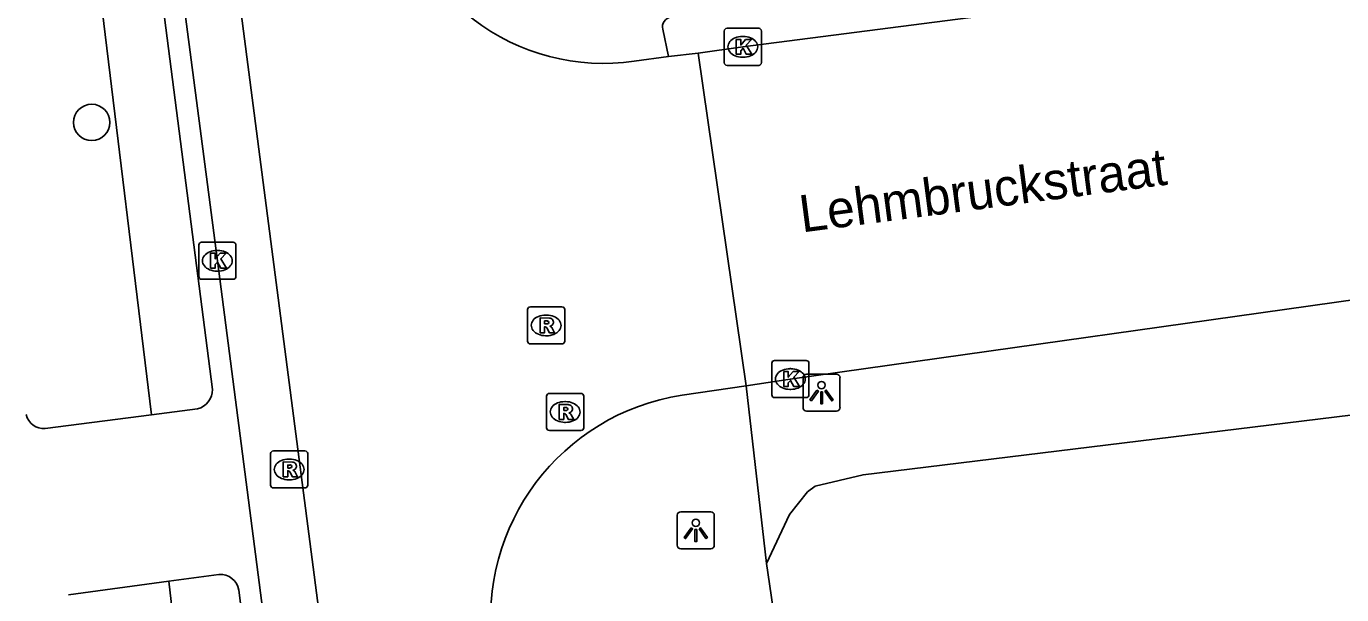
# Model space of a CAD drawing. Extents: x 160557 to 161245, y 385330 to 386505.
# Drawn here: x 161105.66 to 161141.1, y 385716.99 to 385732.31 of the extents above; entities that cross this region are included whole.
import ezdxf

# ---------------------------------------------------------------- set-up
doc = ezdxf.new("R2010")
doc.units = 0
for name, color, linetype in [('IMGEO_Boom', 7, 'Continuous'), ('IMGEO_Fietspad_gesloten', 7, 'Continuous'), ('IMGEO_Groenvoorziening', 7, 'Continuous'), ('IMGEO_Kolk', 7, 'Continuous'), ('IMGEO_Lichtpunt', 7, 'Continuous'), ('IMGEO_Openbare_ruimte_label', 7, 'Continuous'), ('IMGEO_Rijbaan_lokaal_gesloten', 7, 'Continuous'), ('IMGEO_Rijbaan_lokaal_open', 7, 'Continuous'), ('IMGEO_Rioolput', 7, 'Continuous'), ('IMGEO_Voetpad_open', 7, 'Continuous')]:
    doc.layers.add(name, color=color, linetype=linetype)

msp = doc.modelspace()

# ---------------------------------------------------------------- linework, layer by layer
at = {"layer": 'IMGEO_Boom'}
msp.add_circle((161107.423, 385729.722), 0.489, dxfattribs=at)
at = {"layer": 'IMGEO_Fietspad_gesloten'}
msp.add_lwpolyline([(161122.962, 385731.503), (161122.809, 385732.234)], dxfattribs=at)
msp.add_arc((161123.066, 385732.296), 0.265, 96.3414, 193.5563, dxfattribs=at)
at = {"layer": 'IMGEO_Groenvoorziening'}
for points in [[(161107.656, 385733.133), (161109.037, 385721.838)], [(161109.498, 385717.352), (161110.302, 385710.38)]]:
    msp.add_lwpolyline(points, dxfattribs=at)
at = {"layer": 'IMGEO_Kolk'}
for p, q in [((161124.466, 385731.334), (161124.466, 385732.186)), ((161124.541, 385732.26), (161125.393, 385732.26)), ((161124.954, 385732.04), (161124.979, 385732.04)), ((161125.467, 385732.186), (161125.467, 385731.334)), ((161124.977, 385731.48), (161124.952, 385731.48)), ((161125.393, 385731.26), (161124.541, 385731.26)), ((161110.307, 385725.566), (161110.307, 385726.418)), ((161110.382, 385726.492), (161111.234, 385726.492)), ((161111.308, 385726.418), (161111.308, 385725.566)), ((161110.795, 385726.272), (161110.82, 385726.272)), ((161110.818, 385725.712), (161110.793, 385725.712)), ((161111.234, 385725.492), (161110.382, 385725.492)), ((161125.747, 385722.376), (161125.747, 385723.228)), ((161125.822, 385723.302), (161126.674, 385723.302)), ((161126.748, 385723.228), (161126.748, 385722.376)), ((161126.235, 385723.082), (161126.26, 385723.082)), ((161126.258, 385722.522), (161126.233, 385722.522)), ((161126.674, 385722.302), (161125.822, 385722.302))]:
    msp.add_line(p, q, dxfattribs=at)
for points in [[(161124.466, 385731.334), (161124.466, 385732.186)], [(161124.541, 385732.26), (161125.393, 385732.26)], [(161125.467, 385732.186), (161125.467, 385731.334)], [(161124.787, 385731.96), (161124.91, 385731.96), (161124.91, 385731.809), (161125.04, 385731.96), (161125.204, 385731.96), (161125.058, 385731.809), (161125.211, 385731.56), (161125.059, 385731.56), (161124.974, 385731.724), (161124.91, 385731.657), (161124.91, 385731.56), (161124.787, 385731.56), (161124.787, 385731.96)], [(161125.393, 385731.26), (161124.541, 385731.26)], [(161110.307, 385725.566), (161110.307, 385726.418)], [(161110.382, 385726.492), (161111.234, 385726.492)], [(161111.308, 385726.418), (161111.308, 385725.566)], [(161110.628, 385726.192), (161110.751, 385726.192), (161110.751, 385726.041), (161110.881, 385726.192), (161111.045, 385726.192), (161110.899, 385726.041), (161111.052, 385725.792), (161110.9, 385725.792), (161110.815, 385725.956), (161110.751, 385725.889), (161110.751, 385725.792), (161110.628, 385725.792), (161110.628, 385726.192)], [(161111.234, 385725.492), (161110.382, 385725.492)], [(161125.747, 385722.376), (161125.747, 385723.228)], [(161125.822, 385723.302), (161126.674, 385723.302)], [(161126.748, 385723.228), (161126.748, 385722.376)], [(161126.068, 385723.002), (161126.191, 385723.002), (161126.191, 385722.851), (161126.321, 385723.002), (161126.485, 385723.002), (161126.339, 385722.851), (161126.492, 385722.602), (161126.34, 385722.602), (161126.255, 385722.766), (161126.191, 385722.699), (161126.191, 385722.602), (161126.068, 385722.602), (161126.068, 385723.002)], [(161126.674, 385722.302), (161125.822, 385722.302)]]:
    msp.add_lwpolyline(points, dxfattribs=at)
for centre, start, end in [((161124.543, 385732.184), 91.552, 178.448), ((161124.543, 385732.184), 91.552, 178.448), ((161125.391, 385732.184), 1.552, 88.448), ((161125.391, 385732.184), 1.552, 88.448), ((161124.543, 385731.336), 181.552, 268.448), ((161124.543, 385731.336), 181.552, 268.448), ((161125.391, 385731.336), 271.552, 358.448), ((161125.391, 385731.336), 271.552, 358.448), ((161110.384, 385726.416), 91.552, 178.448), ((161110.384, 385726.416), 91.552, 178.448), ((161111.232, 385726.416), 1.552, 88.448), ((161111.232, 385726.416), 1.552, 88.448), ((161110.384, 385725.568), 181.552, 268.448), ((161110.384, 385725.568), 181.552, 268.448), ((161111.232, 385725.568), 271.552, 358.448), ((161111.232, 385725.568), 271.552, 358.448), ((161125.824, 385723.226), 91.552, 178.448), ((161125.824, 385723.226), 91.552, 178.448), ((161126.672, 385723.226), 1.552, 88.448), ((161126.672, 385723.226), 1.552, 88.448), ((161125.824, 385722.378), 181.552, 268.448), ((161125.824, 385722.378), 181.552, 268.448), ((161126.672, 385722.378), 271.552, 358.448), ((161126.672, 385722.378), 271.552, 358.448)]:
    msp.add_arc(centre, 0.0765, start, end, dxfattribs=at)
for centre, major_axis, ratio, start_param, end_param in [((161124.953, 385731.76), (-0.387, 0.002), 0.722429, 4.712389, 7.853982), ((161124.978, 385731.76), (-0.39, 0.002), 0.717154, 1.570796, 4.712389), ((161110.794, 385725.992), (-0.387, 0.002), 0.722429, 4.712389, 7.853982), ((161110.819, 385725.992), (-0.39, 0.002), 0.717154, 1.570796, 4.712389), ((161126.234, 385722.802), (-0.387, 0.002), 0.722429, 4.712389, 7.853982), ((161126.259, 385722.802), (-0.39, 0.002), 0.717154, 1.570796, 4.712389)]:
    msp.add_ellipse(centre, major_axis=major_axis, ratio=ratio, start_param=start_param, end_param=end_param, dxfattribs=at)
at = {"layer": 'IMGEO_Lichtpunt'}
for p, q in [((161126.588, 385722.841), (161126.588, 385722.034)), ((161126.588, 385722.841), (161126.588, 385722.034)), ((161127.49, 385722.936), (161126.682, 385722.936)), ((161127.49, 385722.936), (161126.682, 385722.936)), ((161127.584, 385722.034), (161127.584, 385722.841)), ((161127.584, 385722.034), (161127.584, 385722.841)), ((161126.682, 385721.94), (161127.49, 385721.94)), ((161126.682, 385721.94), (161127.49, 385721.94)), ((161124.103, 385719.222), (161123.295, 385719.222)), ((161124.103, 385719.222), (161123.295, 385719.222)), ((161123.201, 385719.127), (161123.201, 385718.32)), ((161123.201, 385719.127), (161123.201, 385718.32)), ((161124.197, 385718.32), (161124.197, 385719.127)), ((161124.197, 385718.32), (161124.197, 385719.127)), ((161123.295, 385718.226), (161124.103, 385718.226)), ((161123.295, 385718.226), (161124.103, 385718.226))]:
    msp.add_line(p, q, dxfattribs=at)
for points in [[(161126.962, 385722.505), (161127.001, 385722.477), (161126.813, 385722.215), (161126.775, 385722.242), (161126.962, 385722.505)], [(161127.064, 385722.457), (161127.111, 385722.457), (161127.111, 385722.135), (161127.064, 385722.135), (161127.064, 385722.457)], [(161127.174, 385722.477), (161127.212, 385722.504), (161127.399, 385722.242), (161127.36, 385722.214), (161127.174, 385722.477)], [(161123.575, 385718.791), (161123.614, 385718.763), (161123.426, 385718.501), (161123.388, 385718.528), (161123.575, 385718.791)], [(161123.677, 385718.743), (161123.724, 385718.743), (161123.724, 385718.421), (161123.677, 385718.421), (161123.677, 385718.743)], [(161123.787, 385718.763), (161123.825, 385718.79), (161124.012, 385718.528), (161123.973, 385718.5), (161123.787, 385718.763)]]:
    msp.add_lwpolyline(points, dxfattribs=at)
for centre in [(161127.087, 385722.639), (161123.7, 385718.925)]:
    msp.add_circle(centre, 0.0994, dxfattribs=at)
for centre, start, end in [((161126.682, 385722.841), 90, 180), ((161126.682, 385722.841), 90, 180), ((161127.49, 385722.841), 0, 90), ((161127.49, 385722.841), 0, 90), ((161126.682, 385722.034), 180, 270), ((161126.682, 385722.034), 180, 270), ((161127.49, 385722.034), 270, 0), ((161127.49, 385722.034), 270, 360), ((161123.295, 385719.127), 90, 180), ((161123.295, 385719.127), 90, 180), ((161124.103, 385719.127), 0, 90), ((161124.103, 385719.127), 0, 90), ((161123.295, 385718.32), 180, 270), ((161123.295, 385718.32), 180, 270), ((161124.103, 385718.32), 270, 0), ((161124.103, 385718.32), 270, 360)]:
    msp.add_arc(centre, 0.0946, start, end, dxfattribs=at)
at = {"layer": 'IMGEO_Rijbaan_lokaal_gesloten'}
for points in [[(161156.186, 385735.803), (161142.998, 385734.087), (161140.183, 385733.73), (161124.967, 385731.76), (161123.761, 385731.592)], [(161112.32, 385714.335), (161110.808, 385725.992), (161109.906, 385732.917), (161109.885, 385733.092)], [(161148.145, 385725.902), (161142.936, 385725.157), (161126.238, 385722.801), (161125.06, 385722.618)]]:
    msp.add_lwpolyline(points, dxfattribs=at)
at = {"layer": 'IMGEO_Rijbaan_lokaal_open'}
for points in [[(161109.114, 385739.295), (161110.567, 385739.457), (161113.803, 385714.55), (161112.32, 385714.335)], [(161122.962, 385731.503), (161122.041, 385731.376)], [(161123.761, 385731.592), (161122.962, 385731.503)], [(161125.06, 385722.618), (161123.761, 385731.592)], [(161123.329, 385722.367), (161125.06, 385722.618)]]:
    msp.add_lwpolyline(points, dxfattribs=at)
for centre, radius, start, end in [((161121.199, 385737.038), 5.725, 186.1502, 278.4614), ((161124.257, 385716.353), 6.085, 98.7712, 187.3487)]:
    msp.add_arc(centre, radius, start, end, dxfattribs=at)
at = {"layer": 'IMGEO_Rioolput'}
for p, q in [((161119.166, 385723.823), (161119.166, 385724.675)), ((161119.241, 385724.749), (161120.093, 385724.749)), ((161120.167, 385724.675), (161120.167, 385723.823)), ((161119.654, 385724.529), (161119.679, 385724.529)), ((161119.677, 385723.969), (161119.652, 385723.969)), ((161120.093, 385723.749), (161119.241, 385723.749)), ((161119.754, 385722.414), (161120.606, 385722.414)), ((161119.679, 385721.488), (161119.679, 385722.34)), ((161120.167, 385722.194), (161120.192, 385722.194)), ((161120.68, 385722.34), (161120.68, 385721.488)), ((161120.606, 385721.414), (161119.754, 385721.414)), ((161120.19, 385721.634), (161120.165, 385721.634)), ((161112.242, 385719.939), (161112.242, 385720.791)), ((161112.317, 385720.865), (161113.169, 385720.865)), ((161112.73, 385720.645), (161112.755, 385720.645)), ((161113.243, 385720.791), (161113.243, 385719.939)), ((161112.753, 385720.085), (161112.728, 385720.085)), ((161113.169, 385719.865), (161112.317, 385719.865))]:
    msp.add_line(p, q, dxfattribs=at)
for points in [[(161119.166, 385723.823), (161119.166, 385724.675)], [(161119.241, 385724.749), (161120.093, 385724.749)], [(161120.167, 385724.675), (161120.167, 385723.823)], [(161119.755, 385724.447), (161119.503, 385724.449), (161119.503, 385724.049)], [(161119.503, 385724.049), (161119.627, 385724.049), (161119.627, 385724.211), (161119.638, 385724.211)], [(161119.681, 385724.368), (161119.627, 385724.368), (161119.627, 385724.287)], [(161119.627, 385724.287), (161119.679, 385724.287)], [(161119.685, 385724.182), (161119.756, 385724.049), (161119.896, 385724.049), (161119.831, 385724.175)], [(161120.093, 385723.749), (161119.241, 385723.749)], [(161119.754, 385722.414), (161120.606, 385722.414)], [(161119.679, 385721.488), (161119.679, 385722.34)], [(161120.268, 385722.112), (161120.016, 385722.114), (161120.016, 385721.714)], [(161120.68, 385722.34), (161120.68, 385721.488)], [(161120.016, 385721.714), (161120.14, 385721.714), (161120.14, 385721.876), (161120.151, 385721.876)], [(161120.194, 385722.033), (161120.14, 385722.033), (161120.14, 385721.952)], [(161120.14, 385721.952), (161120.192, 385721.952)], [(161120.198, 385721.847), (161120.269, 385721.714), (161120.409, 385721.714), (161120.344, 385721.84)], [(161120.606, 385721.414), (161119.754, 385721.414)], [(161112.242, 385719.939), (161112.242, 385720.791)], [(161112.317, 385720.865), (161113.169, 385720.865)], [(161113.243, 385720.791), (161113.243, 385719.939)], [(161112.831, 385720.563), (161112.579, 385720.565), (161112.579, 385720.165)], [(161112.579, 385720.165), (161112.703, 385720.165), (161112.703, 385720.327), (161112.714, 385720.327)], [(161112.757, 385720.484), (161112.703, 385720.484), (161112.703, 385720.403)], [(161112.703, 385720.403), (161112.755, 385720.403)], [(161112.761, 385720.298), (161112.832, 385720.165), (161112.972, 385720.165), (161112.907, 385720.291)], [(161113.169, 385719.865), (161112.317, 385719.865)]]:
    msp.add_lwpolyline(points, dxfattribs=at)
for centre, radius, start, end in [((161119.243, 385724.673), 0.0765, 91.552, 178.448), ((161119.243, 385724.673), 0.0765, 91.552, 178.448), ((161120.091, 385724.673), 0.0765, 1.552, 88.448), ((161120.091, 385724.673), 0.0765, 1.552, 88.448), ((161119.637, 385724.158), 0.0533, 26.0293, 88.6989), ((161119.663, 385724.476), 0.19, 274.7715, 282.9687), ((161119.687, 385724.272), 0.0964, 77.0061, 93.1865), ((161119.701, 385724.329), 0.0378, 276.6634, 79.6772), ((161119.754, 385724.337), 0.109, 350.3612, 89.416), ((161119.752, 385724.337), 0.112, 277.5842, 350.9817), ((161119.736, 385724.122), 0.108, 29.5134, 73.7905), ((161119.243, 385723.825), 0.0765, 181.552, 268.448), ((161119.243, 385723.825), 0.0765, 181.552, 268.448), ((161120.091, 385723.825), 0.0765, 271.552, 358.448), ((161120.091, 385723.825), 0.0765, 271.552, 358.448), ((161119.756, 385722.338), 0.0765, 91.552, 178.448), ((161119.756, 385722.338), 0.0765, 91.552, 178.448), ((161120.604, 385722.338), 0.0765, 1.552, 88.448), ((161120.604, 385722.338), 0.0765, 1.552, 88.448), ((161120.267, 385722.002), 0.109, 350.3612, 89.416), ((161120.15, 385721.823), 0.0533, 26.0293, 88.6989), ((161120.176, 385722.141), 0.19, 274.7715, 282.9687), ((161120.2, 385721.937), 0.0964, 77.0061, 93.1865), ((161120.214, 385721.994), 0.0378, 276.6634, 79.6772), ((161120.265, 385722.002), 0.112, 277.5842, 350.9817), ((161120.249, 385721.787), 0.108, 29.5134, 73.7905), ((161119.756, 385721.49), 0.0765, 181.552, 268.448), ((161119.756, 385721.49), 0.0765, 181.552, 268.448), ((161120.604, 385721.49), 0.0765, 271.552, 358.448), ((161120.604, 385721.49), 0.0765, 271.552, 358.448), ((161112.319, 385720.789), 0.0765, 91.552, 178.448), ((161112.319, 385720.789), 0.0765, 91.552, 178.448), ((161113.167, 385720.789), 0.0765, 1.552, 88.448), ((161113.167, 385720.789), 0.0765, 1.552, 88.448), ((161112.713, 385720.274), 0.0533, 26.0293, 88.6989), ((161112.739, 385720.592), 0.19, 274.7715, 282.9687), ((161112.763, 385720.388), 0.0964, 77.0061, 93.1865), ((161112.777, 385720.445), 0.0378, 276.6634, 79.6772), ((161112.83, 385720.453), 0.109, 350.3612, 89.416), ((161112.828, 385720.453), 0.112, 277.5842, 350.9817), ((161112.812, 385720.238), 0.108, 29.5134, 73.7905), ((161112.319, 385719.941), 0.0765, 181.552, 268.448), ((161112.319, 385719.941), 0.0765, 181.552, 268.448), ((161113.167, 385719.941), 0.0765, 271.552, 358.448), ((161113.167, 385719.941), 0.0765, 271.552, 358.448)]:
    msp.add_arc(centre, radius, start, end, dxfattribs=at)
for centre, major_axis, ratio, start_param, end_param in [((161119.653, 385724.249), (-0.387, 0.002), 0.722429, 4.712389, 7.853982), ((161119.678, 385724.249), (-0.39, 0.002), 0.717154, 1.570796, 4.712389), ((161120.166, 385721.914), (-0.387, 0.002), 0.722429, 4.712389, 7.853982), ((161120.191, 385721.914), (-0.39, 0.002), 0.717154, 1.570796, 4.712389), ((161112.729, 385720.365), (-0.387, 0.002), 0.722429, 4.712389, 7.853982), ((161112.754, 385720.365), (-0.39, 0.002), 0.717154, 1.570796, 4.712389)]:
    msp.add_ellipse(centre, major_axis=major_axis, ratio=ratio, start_param=start_param, end_param=end_param, dxfattribs=at)
at = {"layer": 'IMGEO_Voetpad_open'}
for points in [[(161109.344, 385732.833), (161110.674, 385722.524)], [(161125.06, 385722.618), (161125.602, 385717.829)], [(161147.059, 385722.533), (161128.206, 385720.222), (161126.919, 385719.912), (161126.713, 385719.758), (161126.224, 385719.145), (161125.602, 385717.829)], [(161109.037, 385721.838), (161106.173, 385721.467)], [(161110.273, 385721.998), (161109.037, 385721.838)], [(161125.602, 385717.829), (161127.611, 385704.206)], [(161109.498, 385717.352), (161110.851, 385717.535)], [(161106.795, 385716.986), (161109.498, 385717.352)], [(161111.39, 385717.113), (161112.143, 385711.099)]]:
    msp.add_lwpolyline(points, dxfattribs=at)
for centre, radius, start, end in [((161110.14, 385722.515), 0.534, 284.4297, 0.9296), ((161106.129, 385721.944), 0.479, 192.0028, 275.2667), ((161110.887, 385717.026), 0.51, 9.8059, 94.0771)]:
    msp.add_arc(centre, radius, start, end, dxfattribs=at)

# ---------------------------------------------------------------- texts
at = {"layer": 'IMGEO_Openbare_ruimte_label'}
msp.add_text('Lehmbruckstraat', height=1, rotation=7.466, dxfattribs=at).set_placement((161126.558, 385726.753))

doc.saveas('drawing.dxf')
